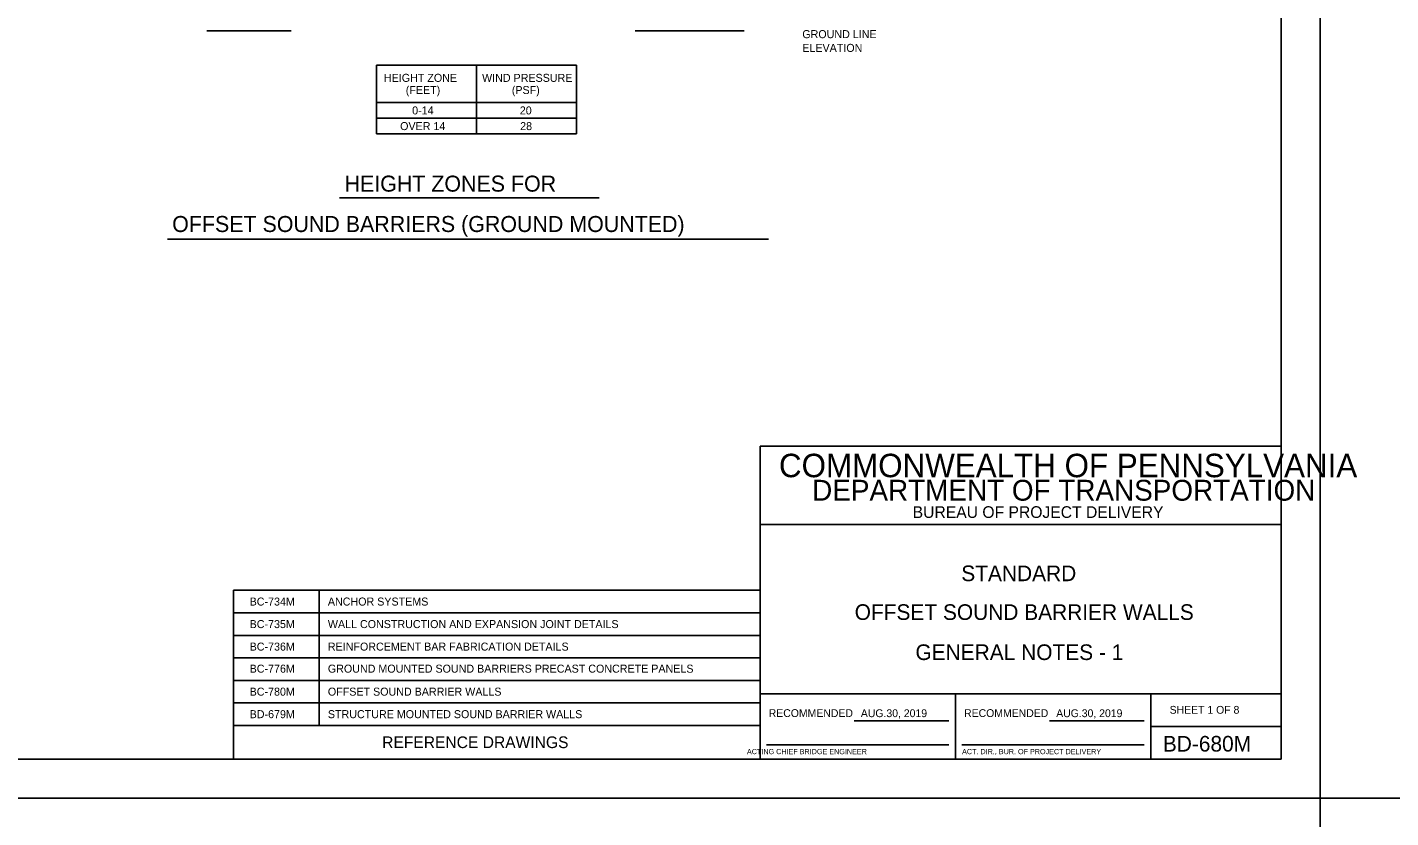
# Model space of a CAD drawing. Extents: x 3385 to 6532, y -616 to 1166.
# Drawn here: x 4106 to 4629, y 564 to 867 of the extents above; entities that cross this region are included whole.
import ezdxf

# ---------------------------------------------------------------- set-up
doc = ezdxf.new("R2010")
doc.units = 0
for name, color, linetype in [('1', 7, 'Continuous'), ('2', 7, 'Continuous'), ('PLT-BNDY', 7, 'Continuous')]:
    doc.layers.add(name, color=color, linetype=linetype)

msp = doc.modelspace()

# ---------------------------------------------------------------- linework, layer by layer
at = {"layer": '1'}
for p, q in [((4174.95, 866.05), (4207.37, 866.05)), ((4339.41, 866.05), (4381.22, 866.05)), ((4240.04, 852.93), (4240.04, 826.53)), ((4240.04, 852.93), (4316.84, 852.93)), ((4278.44, 852.93), (4278.44, 826.53)), ((4316.84, 852.93), (4316.84, 826.53)), ((4240.04, 838.53), (4316.84, 838.53)), ((4240.04, 832.53), (4316.84, 832.53)), ((4240.04, 826.53), (4316.84, 826.53)), ((4225.89, 801.99), (4325.55, 801.99)), ((4159.88, 786.13), (4390.56, 786.13)), ((4185.2, 651.43), (4185.2, 586.69)), ((4185.2, 651.43), (4387.34, 651.43)), ((4218.03, 651.43), (4218.03, 599.59)), ((4185.2, 642.79), (4387.34, 642.79)), ((4185.2, 634.15), (4387.34, 634.15)), ((4185.2, 625.51), (4387.34, 625.51)), ((4185.2, 616.87), (4387.34, 616.87)), ((4185.2, 608.23), (4387.34, 608.23)), ((4462.34, 586.69), (4462.34, 611.69)), ((4185.2, 599.59), (4387.34, 599.59)), ((4423.43, 601.41), (4459.84, 601.41)), ((4498.43, 601.41), (4534.84, 601.41)), ((4389.84, 592.19), (4459.84, 592.19)), ((4464.84, 592.19), (4534.84, 592.19))]:
    msp.add_line(p, q, dxfattribs=at)
at = {"layer": '2'}
for p, q in [((4587.34, 1150.69), (4587.34, 586.69)), ((4587.34, 706.69), (4387.34, 706.69)), ((4387.34, 706.69), (4387.34, 586.69)), ((4587.34, 586.69), (4587.34, 706.69)), ((4587.34, 676.69), (4387.34, 676.69)), ((4587.34, 611.69), (4387.34, 611.69)), ((4537.34, 611.69), (4537.34, 586.69)), ((4537.34, 599.19), (4587.34, 599.19)), ((4587.34, 586.69), (3801.34, 586.69)), ((4387.34, 586.69), (4587.34, 586.69))]:
    msp.add_line(p, q, dxfattribs=at)
at = {"layer": 'PLT-BNDY'}
for points in [[(3761.34, 1165.69), (4602.34, 1165.69), (4602.34, 571.69), (3761.34, 571.69)], [(4602.34, 1165.69), (5443.34, 1165.69), (5443.34, 571.69), (4602.34, 571.69)], [(3761.34, 571.69), (4602.34, 571.69), (4602.34, -22.31), (3761.34, -22.31)], [(4602.34, 571.69), (5443.34, 571.69), (5443.34, -22.31), (4602.34, -22.31)]]:
    msp.add_lwpolyline(points, close=True, dxfattribs=at)

# ---------------------------------------------------------------- texts
at = {"layer": '1'}
for s, height, p in [('GROUND LINE', 3.072, (4403.55, 863.26)), ('ELEVATION', 3.072, (4403.55, 857.99)), ('HEIGHT ZONE', 3.072, (4242.94, 846.5)), ('WIND PRESSURE', 3.072, (4280.61, 846.5)), ('(FEET)', 3.072, (4251.32, 841.83)), ('(PSF)', 3.072, (4292.03, 841.83)), ('0-14', 3.072, (4253.76, 834)), ('20', 3.072, (4295.1, 834)), ('OVER 14', 3.072, (4249.15, 827.99)), ('28', 3.072, (4295.23, 827.99)), ('HEIGHT ZONES FOR', 6.144, (4227.8, 804.38)), ('OFFSET SOUND BARRIERS (GROUND MOUNTED)', 6.144, (4161.64, 788.89)), ('STANDARD', 6, (4464.59, 654.94)), ('BC-734M', 3.072, (4191.38, 645.58)), ('ANCHOR SYSTEMS', 3.072, (4221.41, 645.58)), ('OFFSET SOUND BARRIER WALLS', 6.0001, (4423.67, 640.07)), ('BC-735M', 3.072, (4191.38, 636.94)), ('WALL CONSTRUCTION AND EXPANSION JOINT DETAILS', 3.072, (4221.41, 636.94)), ('BC-736M', 3.072, (4191.38, 628.3)), ('REINFORCEMENT BAR FABRICATION DETAILS', 3.072, (4221.41, 628.3)), ('GENERAL NOTES - 1', 6.0001, (4446.99, 624.69)), ('BC-776M', 3.072, (4191.38, 619.84)), ('GROUND MOUNTED SOUND BARRIERS PRECAST CONCRETE PANELS', 3.072, (4221.41, 619.84)), ('BC-780M', 3.072, (4191.38, 611.02)), ('OFFSET SOUND BARRIER WALLS', 3.072, (4221.41, 611.02)), ('BD-679M', 3.072, (4191.38, 602.38)), ('STRUCTURE MOUNTED SOUND BARRIER WALLS', 3.072, (4221.41, 602.38)), ('RECOMMENDED', 3, (4390.67, 602.82)), ('AUG.30, 2019', 3, (4426.03, 602.78)), ('RECOMMENDED', 3, (4465.67, 602.82)), ('AUG.30, 2019', 3, (4501.03, 602.78)), ('SHEET 1 OF 8', 3, (4544.59, 604.08)), ('REFERENCE DRAWINGS', 4.4775, (4242.26, 590.9)), ('BD-680M', 6, (4541.97, 589.57)), ('       ACTING CHIEF BRIDGE ENGINEER', 2.0002, (4376.93, 588.57)), ('ACT. DIR., BUR. OF PROJECT DELIVERY', 2.0002, (4464.88, 588.57))]:
    msp.add_text(s, height=height, dxfattribs=at).set_placement(p)
at = {"layer": '2'}
for s, height, p in [('COMMONWEALTH OF PENNSYLVANIA', 9, (4394.59, 694.82)), ('DEPARTMENT OF TRANSPORTATION', 8.0002, (4407.34, 685.82)), ('BUREAU OF PROJECT DELIVERY', 4.5, (4445.93, 679.19))]:
    msp.add_text(s, height=height, dxfattribs=at).set_placement(p)

doc.saveas('drawing.dxf')
